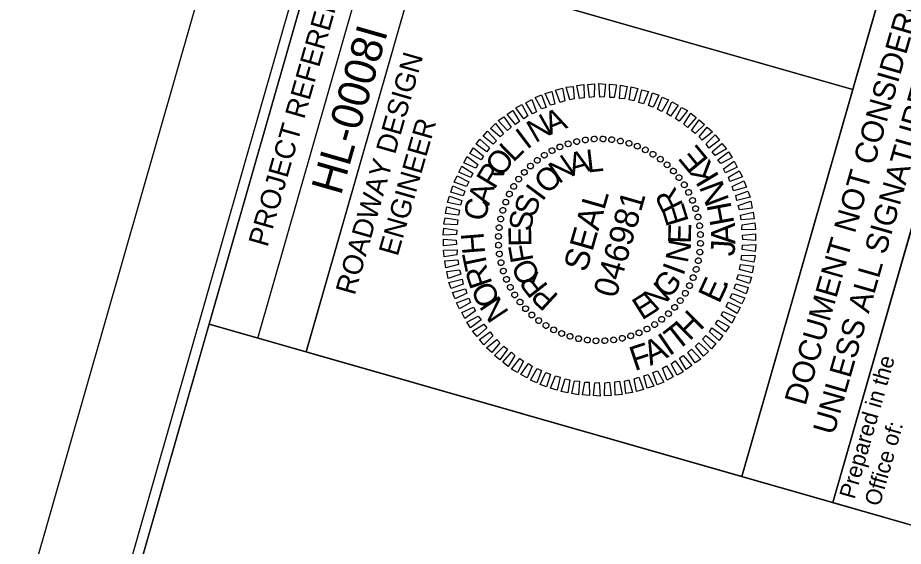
# Model space of a CAD drawing. Extents: x 2096988 to 2098509, y 687711 to 689775.
# Drawn here: x 2097368.1 to 2097587.9, y 689361.6 to 689492.9 of the extents above; entities that cross this region are included whole.
import ezdxf

# ---------------------------------------------------------------- set-up
doc = ezdxf.new("R2010")
doc.units = 0
for name, color, linetype in [('Sheet Block Title CELL', 7, 'Continuous'), ('Sheet Data Field CELL', 7, 'Continuous'), ('Sheet Layout Plan Border', 7, 'Continuous'), ('Sheet PE Seal Cell', 7, 'Continuous'), ('Sheet Plot Border Inside CELL', 7, 'Continuous'), ('Sheet Plot Border Outside CELL', 7, 'Continuous'), ('Sheet Profile CELL', 7, 'Continuous'), ('Sheet Sticker Exception Certification CELL', 7, 'Continuous')]:
    doc.layers.add(name, color=color, linetype=linetype)

msp = doc.modelspace()

# ---------------------------------------------------------------- linework, layer by layer
at = {"layer": 'Sheet Block Title CELL'}
msp.add_lwpolyline([(2097570.41, 689372.44), (2097625.47, 689564.78), (2097650.71, 689557.55), (2097595.66, 689365.22)], close=True, dxfattribs=at)
at = {"layer": 'Sheet Layout Plan Border'}
msp.add_lwpolyline([(2098117.8, 688054.49), (2097347.73, 688084.03), (2097057.83, 688167.01), (2097415.58, 689416.76), (2097595.66, 689365.22), (2097650.71, 689557.55), (2098480.09, 689320.13)], close=True, dxfattribs=at)
at = {"layer": 'Sheet PE Seal Cell'}
for p, q in [((2097508.97, 689462.59), (2097508.97, 689462.59)), ((2097511.11, 689462.81), (2097511.11, 689462.81)), ((2097513.3, 689462.81), (2097513.3, 689462.81)), ((2097515.52, 689462.59), (2097515.52, 689462.59)), ((2097502.65, 689460.86), (2097502.65, 689460.86)), ((2097504.68, 689461.58), (2097504.68, 689461.58)), ((2097506.82, 689462.16), (2097506.82, 689462.16)), ((2097517.67, 689462.28), (2097517.67, 689462.28)), ((2097519.8, 689461.73), (2097519.8, 689461.73)), ((2097521.88, 689460.98), (2097521.88, 689460.98)), ((2097498.78, 689458.8), (2097498.78, 689458.8)), ((2097500.65, 689459.87), (2097500.65, 689459.87)), ((2097523.85, 689460.05), (2097523.85, 689460.05)), ((2097525.74, 689459.04), (2097525.74, 689459.04)), ((2097495.31, 689456.1), (2097495.31, 689456.1)), ((2097497.01, 689457.49), (2097497.01, 689457.49)), ((2097527.57, 689457.79), (2097527.57, 689457.79)), ((2097529.24, 689456.37), (2097529.24, 689456.37)), ((2097493.81, 689454.5), (2097493.81, 689454.5)), ((2097530.84, 689454.87), (2097530.84, 689454.87)), ((2097492.39, 689452.82), (2097492.39, 689452.82)), ((2097532.23, 689453.18), (2097532.23, 689453.18)), ((2097491.14, 689451), (2097491.14, 689451)), ((2097533.54, 689451.4), (2097533.54, 689451.4)), ((2097534.62, 689449.53), (2097534.62, 689449.53)), ((2097490.13, 689449.1), (2097490.13, 689449.1)), ((2097535.61, 689447.53), (2097535.61, 689447.53)), ((2097488.46, 689445.06), (2097488.46, 689445.06)), ((2097489.2, 689447.13), (2097489.2, 689447.13)), ((2097536.33, 689445.5), (2097536.33, 689445.5)), ((2097487.9, 689442.93), (2097487.9, 689442.93)), ((2097536.91, 689443.36), (2097536.91, 689443.36)), ((2097487.59, 689440.78), (2097487.59, 689440.78)), ((2097537.33, 689441.21), (2097537.33, 689441.21)), ((2097487.37, 689438.56), (2097487.37, 689438.56)), ((2097537.55, 689439.07), (2097537.55, 689439.07)), ((2097487.37, 689436.37), (2097487.37, 689436.37)), ((2097512.46, 689437.72), (2097512.46, 689437.72)), ((2097537.55, 689436.88), (2097537.55, 689436.88)), ((2097487.59, 689434.23), (2097487.59, 689434.23)), ((2097537.33, 689434.66), (2097537.33, 689434.66)), ((2097488.02, 689432.08), (2097488.02, 689432.08)), ((2097537.03, 689432.51), (2097537.03, 689432.51)), ((2097488.6, 689429.94), (2097488.6, 689429.94)), ((2097536.47, 689430.38), (2097536.47, 689430.38)), ((2097489.32, 689427.91), (2097489.32, 689427.91)), ((2097535.72, 689428.3), (2097535.72, 689428.3)), ((2097490.31, 689425.91), (2097490.31, 689425.91)), ((2097534.79, 689426.33), (2097534.79, 689426.33)), ((2097491.38, 689424.04), (2097491.38, 689424.04)), ((2097533.78, 689424.44), (2097533.78, 689424.44)), ((2097492.7, 689422.26), (2097492.7, 689422.26)), ((2097531.11, 689420.94), (2097531.11, 689420.94)), ((2097532.53, 689422.61), (2097532.53, 689422.61)), ((2097494.08, 689420.56), (2097494.08, 689420.56)), ((2097495.68, 689419.07), (2097495.68, 689419.07)), ((2097529.62, 689419.34), (2097529.62, 689419.34)), ((2097497.36, 689417.65), (2097497.36, 689417.65)), ((2097499.18, 689416.4), (2097499.18, 689416.4)), ((2097526.14, 689416.64), (2097526.14, 689416.64)), ((2097527.92, 689417.95), (2097527.92, 689417.95)), ((2097501.08, 689415.39), (2097501.08, 689415.39)), ((2097503.05, 689414.46), (2097503.05, 689414.46)), ((2097522.27, 689414.58), (2097522.27, 689414.58)), ((2097524.27, 689415.56), (2097524.27, 689415.56)), ((2097505.12, 689413.71), (2097505.12, 689413.71)), ((2097507.25, 689413.15), (2097507.25, 689413.15)), ((2097509.4, 689412.85), (2097509.4, 689412.85)), ((2097511.63, 689412.63), (2097511.63, 689412.63)), ((2097513.81, 689412.63), (2097513.81, 689412.63)), ((2097515.95, 689412.85), (2097515.95, 689412.85)), ((2097518.1, 689413.27), (2097518.1, 689413.27)), ((2097520.25, 689413.86), (2097520.25, 689413.86))]:
    msp.add_line(p, q, dxfattribs=at)
for points in [[(2097505.14, 689472.47), (2097504.23, 689475.65), (2097505.9, 689475.85), (2097506.22, 689472.79)], [(2097507.49, 689472.84), (2097506.86, 689476.09), (2097508.57, 689476.28), (2097508.68, 689473.02)], [(2097509.99, 689473.06), (2097509.58, 689476.35), (2097511.22, 689476.45), (2097511.14, 689473.25)], [(2097512.52, 689473.17), (2097512.3, 689476.56), (2097513.97, 689476.4), (2097513.63, 689473.22)], [(2097514.99, 689473.09), (2097514.95, 689476.38), (2097516.66, 689476.2), (2097516.09, 689473.09)], [(2097517.42, 689472.86), (2097517.65, 689476.18), (2097519.32, 689475.85), (2097518.63, 689472.72)], [(2097498.06, 689470.24), (2097496.53, 689473.07), (2097498.11, 689473.71), (2097499.21, 689470.64)], [(2097500.34, 689471.14), (2097499, 689474.08), (2097500.65, 689474.59), (2097501.42, 689471.46)], [(2097502.67, 689471.83), (2097501.57, 689474.9), (2097503.28, 689475.4), (2097503.83, 689472.23)], [(2097519.81, 689472.49), (2097520.32, 689475.72), (2097521.99, 689475.35), (2097521, 689472.25)], [(2097522.23, 689471.85), (2097522.98, 689475.01), (2097524.62, 689474.55), (2097523.39, 689471.52)], [(2097524.62, 689471.11), (2097525.61, 689474.21), (2097527.17, 689473.66), (2097525.75, 689470.69)], [(2097495.84, 689469.05), (2097494.18, 689471.77), (2097495.66, 689472.59), (2097496.82, 689469.55)], [(2097526.86, 689470.21), (2097528.03, 689473.2), (2097529.61, 689472.54), (2097527.95, 689469.64)], [(2097529.2, 689469.12), (2097530.44, 689471.99), (2097531.98, 689471.19), (2097530.1, 689468.45)], [(2097491.65, 689466.4), (2097489.52, 689468.94), (2097490.93, 689469.89), (2097492.59, 689467.12)], [(2097493.67, 689467.8), (2097491.73, 689470.49), (2097493.21, 689471.31), (2097494.65, 689468.51)], [(2097531.33, 689467.84), (2097532.81, 689470.64), (2097534.3, 689469.85), (2097532.23, 689467.17)], [(2097533.43, 689466.46), (2097535.15, 689469.19), (2097536.46, 689468.14), (2097534.29, 689465.64)], [(2097489.65, 689464.85), (2097487.34, 689467.33), (2097488.71, 689468.29), (2097490.53, 689465.74)], [(2097535.27, 689464.89), (2097537.23, 689467.55), (2097538.51, 689466.41), (2097536.19, 689464.11)], [(2097486.07, 689461.45), (2097483.58, 689463.46), (2097484.68, 689464.76), (2097486.9, 689462.35)], [(2097487.81, 689463.34), (2097485.44, 689465.42), (2097486.67, 689466.63), (2097488.65, 689464.09)], [(2097537.21, 689463.3), (2097539.19, 689465.69), (2097540.48, 689464.54), (2097537.96, 689462.46)], [(2097484.54, 689459.55), (2097481.83, 689461.52), (2097482.79, 689462.7), (2097485.19, 689460.55)], [(2097538.94, 689461.55), (2097541.16, 689463.83), (2097542.23, 689462.48), (2097539.59, 689460.53)], [(2097483.06, 689457.63), (2097480.28, 689459.2), (2097481.19, 689460.56), (2097483.68, 689458.54)], [(2097540.45, 689459.56), (2097542.83, 689461.69), (2097543.96, 689460.37), (2097541.19, 689458.67)], [(2097481.77, 689455.5), (2097478.78, 689456.88), (2097479.64, 689458.4), (2097482.3, 689456.44)], [(2097541.87, 689457.59), (2097544.46, 689459.56), (2097545.4, 689458.14), (2097542.54, 689456.67)], [(2097480.54, 689453.2), (2097477.59, 689454.51), (2097478.28, 689456.03), (2097481.02, 689454.31)], [(2097543.21, 689455.39), (2097545.89, 689457.28), (2097546.65, 689455.76), (2097543.76, 689454.4)], [(2097544.44, 689453.32), (2097547.16, 689454.83), (2097547.98, 689453.35), (2097544.85, 689452.21)], [(2097479.5, 689451), (2097476.43, 689452.09), (2097477.17, 689453.59), (2097480.02, 689452.1)], [(2097545.38, 689450.97), (2097548.28, 689452.38), (2097548.92, 689450.79), (2097545.74, 689449.88)], [(2097478.66, 689448.64), (2097475.54, 689449.54), (2097476.04, 689451.11), (2097479.04, 689449.78)], [(2097546.3, 689448.73), (2097549.26, 689449.81), (2097549.82, 689448.3), (2097546.57, 689447.51)], [(2097477.95, 689446.35), (2097474.76, 689447), (2097475.26, 689448.57), (2097478.33, 689447.49)], [(2097546.9, 689446.27), (2097550, 689447.31), (2097550.34, 689445.6), (2097547.21, 689445.19)], [(2097477.51, 689443.88), (2097474.28, 689444.23), (2097474.55, 689445.92), (2097477.69, 689445.07)], [(2097477.14, 689441.49), (2097473.84, 689441.6), (2097474.15, 689443.23), (2097477.32, 689442.68)], [(2097547.46, 689443.88), (2097550.59, 689444.64), (2097550.84, 689442.96), (2097547.59, 689442.69)], [(2097477, 689439.03), (2097473.69, 689438.88), (2097473.82, 689440.62), (2097477.05, 689440.11)], [(2097547.86, 689441.47), (2097551.01, 689441.92), (2097551.17, 689440.32), (2097547.81, 689440.19)], [(2097547.96, 689438.9), (2097551.16, 689439.18), (2097551.16, 689437.56), (2097548, 689437.79)], [(2097476.97, 689436.54), (2097473.77, 689436.26), (2097473.76, 689437.88), (2097476.92, 689437.65)], [(2097547.92, 689436.41), (2097551.24, 689436.55), (2097551.11, 689434.82), (2097547.87, 689435.33)], [(2097477.06, 689433.97), (2097473.92, 689433.51), (2097473.75, 689435.12), (2097477.12, 689435.25)], [(2097477.47, 689431.56), (2097474.33, 689430.79), (2097474.09, 689432.48), (2097477.34, 689432.74)], [(2097547.79, 689433.95), (2097551.09, 689433.84), (2097550.78, 689432.21), (2097547.6, 689432.76)], [(2097478.03, 689429.16), (2097474.92, 689428.13), (2097474.58, 689429.84), (2097477.71, 689430.24)], [(2097547.42, 689431.56), (2097550.65, 689431.21), (2097550.37, 689429.52), (2097547.23, 689430.37)], [(2097478.62, 689426.71), (2097475.66, 689425.63), (2097475.11, 689427.14), (2097478.35, 689427.93)], [(2097546.97, 689429.09), (2097550.16, 689428.43), (2097549.66, 689426.86), (2097546.59, 689427.95)], [(2097479.54, 689424.47), (2097476.65, 689423.06), (2097476.01, 689424.65), (2097479.18, 689425.56)], [(2097546.26, 689426.8), (2097549.39, 689425.9), (2097548.88, 689424.33), (2097545.88, 689425.66)], [(2097480.48, 689422.12), (2097477.76, 689420.61), (2097476.94, 689422.09), (2097480.07, 689423.22)], [(2097545.43, 689424.43), (2097548.5, 689423.35), (2097547.76, 689421.84), (2097544.91, 689423.33)], [(2097481.71, 689420.05), (2097479.04, 689418.16), (2097478.28, 689419.68), (2097481.16, 689421.04)], [(2097544.38, 689422.24), (2097547.34, 689420.92), (2097546.64, 689419.41), (2097543.91, 689421.12)], [(2097483.06, 689417.84), (2097480.47, 689415.88), (2097479.52, 689417.3), (2097482.38, 689418.76)], [(2097543.15, 689419.94), (2097546.14, 689418.56), (2097545.29, 689417.04), (2097542.62, 689418.99)], [(2097484.47, 689415.88), (2097482.09, 689413.75), (2097480.96, 689415.06), (2097483.74, 689416.76)], [(2097541.87, 689417.81), (2097544.64, 689416.23), (2097543.73, 689414.88), (2097541.24, 689416.89)], [(2097485.98, 689413.89), (2097483.77, 689411.61), (2097482.7, 689412.95), (2097485.34, 689414.9)], [(2097540.38, 689415.89), (2097543.1, 689413.92), (2097542.13, 689412.74), (2097539.73, 689414.88)], [(2097487.72, 689412.14), (2097485.73, 689409.74), (2097484.45, 689410.89), (2097486.97, 689412.98)], [(2097537.11, 689412.1), (2097539.48, 689410.01), (2097538.25, 689408.81), (2097536.27, 689411.35)], [(2097538.85, 689413.99), (2097541.34, 689411.98), (2097540.24, 689410.68), (2097538.02, 689413.08)], [(2097489.65, 689410.55), (2097487.69, 689407.88), (2097486.41, 689409.03), (2097488.73, 689411.33)], [(2097535.28, 689410.59), (2097537.58, 689408.11), (2097536.22, 689407.15), (2097534.4, 689409.7)], [(2097491.49, 689408.98), (2097489.78, 689406.25), (2097488.46, 689407.3), (2097490.64, 689409.8)], [(2097493.59, 689407.6), (2097492.12, 689404.8), (2097490.63, 689405.59), (2097492.7, 689408.27)], [(2097531.26, 689407.63), (2097533.19, 689404.95), (2097531.71, 689404.12), (2097530.28, 689406.93)], [(2097533.27, 689409.03), (2097535.41, 689406.5), (2097533.99, 689405.55), (2097532.34, 689408.31)], [(2097495.72, 689406.31), (2097494.49, 689403.44), (2097492.95, 689404.25), (2097494.82, 689406.99)], [(2097498.06, 689405.23), (2097496.9, 689402.23), (2097495.32, 689402.89), (2097496.98, 689405.8)], [(2097529.08, 689406.39), (2097530.75, 689403.67), (2097529.26, 689402.85), (2097528.11, 689405.88)], [(2097500.3, 689404.33), (2097499.31, 689401.23), (2097497.75, 689401.78), (2097499.18, 689404.75)], [(2097502.69, 689403.59), (2097501.94, 689400.42), (2097500.31, 689400.89), (2097501.54, 689403.92)], [(2097522.25, 689403.61), (2097523.35, 689400.54), (2097521.65, 689400.04), (2097521.1, 689403.21)], [(2097524.58, 689404.29), (2097525.93, 689401.36), (2097524.27, 689400.85), (2097523.5, 689403.98)], [(2097526.87, 689405.2), (2097528.4, 689402.37), (2097526.81, 689401.73), (2097525.71, 689404.8)], [(2097505.11, 689402.95), (2097504.6, 689399.71), (2097502.94, 689400.09), (2097503.93, 689403.18)], [(2097507.5, 689402.58), (2097507.28, 689399.26), (2097505.6, 689399.58), (2097506.29, 689402.72)], [(2097509.93, 689402.35), (2097509.98, 689399.06), (2097508.26, 689399.24), (2097508.84, 689402.35)], [(2097512.4, 689402.27), (2097512.63, 689398.87), (2097510.96, 689399.04), (2097511.3, 689402.22)], [(2097514.93, 689402.37), (2097515.34, 689399.08), (2097513.7, 689398.98), (2097513.78, 689402.18)], [(2097517.44, 689402.59), (2097518.07, 689399.34), (2097516.35, 689399.16), (2097516.24, 689402.42)], [(2097519.78, 689402.96), (2097520.69, 689399.79), (2097519.02, 689399.59), (2097518.7, 689402.65)]]:
    msp.add_lwpolyline(points, close=True, dxfattribs=at)
for centre, major_axis in [((2097506.81, 689462.15), (-0.162, 0.701)), ((2097508.96, 689462.55), (-0.101, 0.713)), ((2097511.14, 689462.76), (-0.038, 0.719)), ((2097513.33, 689462.78), (0.025, 0.72)), ((2097515.51, 689462.61), (0.087, 0.715)), ((2097517.67, 689462.25), (0.149, 0.704)), ((2097500.68, 689459.86), (-0.338, 0.636)), ((2097502.65, 689460.8), (-0.282, 0.663)), ((2097504.7, 689461.57), (-0.223, 0.685)), ((2097519.78, 689461.71), (0.21, 0.689)), ((2097521.85, 689460.98), (0.269, 0.668)), ((2097523.84, 689460.07), (0.327, 0.642)), ((2097497.01, 689457.47), (-0.444, 0.567)), ((2097498.79, 689458.75), (-0.392, 0.604)), ((2097525.74, 689458.99), (0.381, 0.611)), ((2097527.55, 689457.76), (0.433, 0.575)), ((2097495.35, 689456.05), (-0.491, 0.526)), ((2097529.24, 689456.36), (0.482, 0.535)), ((2097493.82, 689454.49), (-0.535, 0.482)), ((2097530.8, 689454.83), (0.526, 0.491)), ((2097532.22, 689453.17), (0.567, 0.444)), ((2097491.19, 689451), (-0.611, 0.381)), ((2097492.43, 689452.8), (-0.575, 0.433)), ((2097533.49, 689451.39), (0.604, 0.392)), ((2097490.11, 689449.09), (-0.642, 0.327)), ((2097534.6, 689449.5), (0.636, 0.338)), ((2097489.2, 689447.1), (-0.668, 0.269)), ((2097535.54, 689447.53), (0.663, 0.282)), ((2097488.47, 689445.04), (-0.689, 0.21)), ((2097536.31, 689445.48), (0.685, 0.223)), ((2097487.93, 689442.92), (-0.704, 0.149)), ((2097536.9, 689443.37), (0.701, 0.162)), ((2097487.57, 689440.76), (-0.715, 0.087)), ((2097537.3, 689441.22), (0.713, 0.101)), ((2097487.4, 689438.58), (-0.72, 0.025)), ((2097537.51, 689439.04), (0.719, 0.038)), ((2097487.42, 689436.39), (-0.719, -0.038)), ((2097537.53, 689436.85), (0.72, -0.025)), ((2097487.63, 689434.22), (-0.713, -0.101)), ((2097537.36, 689434.67), (0.715, -0.087)), ((2097488.03, 689432.07), (-0.701, -0.162)), ((2097537, 689432.52), (0.704, -0.149)), ((2097488.61, 689429.96), (-0.685, -0.223)), ((2097536.45, 689430.4), (0.689, -0.21)), ((2097489.38, 689427.91), (-0.663, -0.282)), ((2097535.72, 689428.33), (0.668, -0.269)), ((2097490.32, 689425.93), (-0.636, -0.338)), ((2097533.74, 689424.44), (0.611, -0.381)), ((2097534.81, 689426.34), (0.642, -0.327)), ((2097491.43, 689424.05), (-0.604, -0.392)), ((2097492.71, 689422.27), (-0.567, -0.444)), ((2097532.5, 689422.63), (0.575, -0.433)), ((2097494.13, 689420.61), (-0.526, -0.491)), ((2097531.11, 689420.95), (0.535, -0.482)), ((2097495.69, 689419.07), (-0.482, -0.535)), ((2097527.91, 689417.96), (0.444, -0.567)), ((2097529.58, 689419.38), (0.491, -0.526)), ((2097497.38, 689417.68), (-0.433, -0.575)), ((2097499.18, 689416.44), (-0.381, -0.611)), ((2097524.25, 689415.58), (0.338, -0.636)), ((2097526.13, 689416.69), (0.392, -0.604)), ((2097501.09, 689415.37), (-0.327, -0.642)), ((2097503.08, 689414.46), (-0.269, -0.668)), ((2097505.14, 689413.73), (-0.21, -0.689)), ((2097520.22, 689413.87), (0.223, -0.685)), ((2097522.27, 689414.64), (0.282, -0.663)), ((2097507.26, 689413.18), (-0.149, -0.704)), ((2097509.42, 689412.82), (-0.087, -0.715)), ((2097511.6, 689412.65), (-0.025, -0.72)), ((2097513.79, 689412.67), (0.038, -0.719)), ((2097515.96, 689412.88), (0.101, -0.713)), ((2097518.12, 689413.28), (0.162, -0.701))]:
    msp.add_ellipse(centre, major_axis=major_axis, ratio=0.999708, dxfattribs=at)
at = {"layer": 'Sheet Plot Border Inside CELL'}
msp.add_lwpolyline([(2098027.36, 687729.29), (2098485.98, 689331.44), (2097471.62, 689621.81), (2097013, 688019.66)], close=True, dxfattribs=at)
at = {"layer": 'Sheet Plot Border Outside CELL'}
msp.add_lwpolyline([(2098045.36, 687710.62), (2098508.8, 689329.59), (2097451.28, 689632.31), (2096987.84, 688013.34)], close=True, dxfattribs=at)
at = {"layer": 'Sheet Profile CELL'}
for p, q in [((2097427.65, 689413.31), (2097482.7, 689605.64)), ((2097467.2, 689506.06), (2097575.31, 689475.11))]:
    msp.add_line(p, q, dxfattribs=at)
for points in [[(2097470.64, 689609.09), (2097057.83, 688167.01), (2098067.29, 687878.05), (2098480.09, 689320.13)], [(2097415.58, 689416.76), (2097470.64, 689609.09), (2097494.72, 689602.2), (2097439.66, 689409.87)], [(2097467.2, 689506.06), (2097494.72, 689602.2), (2097602.87, 689571.24), (2097575.35, 689475.1)], [(2097439.66, 689409.87), (2097467.2, 689506.06), (2097575.35, 689475.1), (2097547.82, 689378.91)]]:
    msp.add_lwpolyline(points, close=True, dxfattribs=at)
at = {"layer": 'Sheet Sticker Exception Certification CELL'}
for p, q in [((2097547.82, 689378.91), (2097602.87, 689571.22)), ((2097625.46, 689564.76), (2097570.41, 689372.44)), ((2097570.41, 689372.44), (2097547.82, 689378.91))]:
    msp.add_line(p, q, dxfattribs=at)

# ---------------------------------------------------------------- texts
at = {"layer": 'Sheet Block Title CELL'}
for s, height, p in [('Prepared in the ', 4.0012, (2097575.74, 689373.13)), ('Office of:', 4.001, (2097581.99, 689371.34))]:
    msp.add_text(s, height=height, rotation=74.0259, dxfattribs=at).set_placement(p)
at = {"layer": 'Sheet Data Field CELL'}
msp.add_text('HL-0008I', height=7.75, rotation=74.0259, dxfattribs=at).set_placement((2097448.28, 689448.56))
at = {"layer": 'Sheet PE Seal Cell'}
for s, height, rotation, p in [('A', 5.64, 22.643, (2097500.19, 689463.7)), ('N', 5.64, 29.8448, (2097496.54, 689461.68)), ('I', 5.64, 37.046, (2097494.46, 689460.03)), ('L', 5.64, 44.2468, (2097491.04, 689456.8)), ('E', 6, 129.5189, (2097539.77, 689457.57)), ('O', 5.64, 51.4471, (2097488.05, 689453.08)), ('N', 5.64, 34.5025, (2097502.36, 689451.48)), ('A', 5.64, 15.7862, (2097505.64, 689453.5)), ('L', 5.64, 6.4267, (2097509.5, 689454.43)), ('R', 5.64, 58.647, (2097486.4, 689450.07)), ('K', 6, 121.235, (2097542.35, 689453.43)), ('O', 5.64, 43.8594, (2097499.51, 689448.81)), ('I', 5.64, 53.2155, (2097498.29, 689447.08)), ('N', 6, 110.5092, (2097544.75, 689447.59)), ('A', 5.64, 73.0462, (2097485.06, 689446.08)), ('R', 5.64, 116.5073, (2097533.41, 689446.39)), ('C', 5.64, 80.2458, (2097484.26, 689442.2)), ('S', 5.64, 71.9263, (2097496.44, 689443.14)), ('SEAL', 5.998, 74.0259, (2097509.22, 689429.49)), ('046981', 5.998, 74.0259, (2097516.59, 689423.04)), ('E', 5.64, 107.15, (2097534.69, 689442.33)), ('H', 6, 100.5252, (2097545.97, 689441.85)), ('S', 5.64, 81.2815, (2097495.49, 689439.66)), ('E', 5.64, 90.637, (2097495.55, 689436.06)), ('E', 5.64, 88.4377, (2097535.11, 689436.7)), ('A', 6, 91.6849, (2097546.21, 689436.65)), ('H', 5.64, 94.6454, (2097484.09, 689434.35)), ('F', 5.64, 99.9929, (2097496.11, 689432.57)), ('N', 5.64, 79.0823, (2097534.32, 689431.77)), ('J', 6, 86.427, (2097545.97, 689433.56)), ('T', 5.64, 101.8457, (2097484.78, 689430.77)), ('O', 5.64, 118.7071, (2097498.04, 689428.58)), ('I', 5.64, 69.7271, (2097533.25, 689428.59)), ('R', 5.64, 109.0464, (2097485.96, 689426.89)), ('R', 5.64, 128.0655, (2097499.92, 689426.23)), ('G', 5.64, 51.0161, (2097529.62, 689422.82)), ('E', 6, 65.0836, (2097542.16, 689421.65)), ('O', 5.64, 116.2476, (2097487.99, 689422.72)), ('N', 5.64, 41.6598, (2097526.42, 689419.79)), ('.', 6, 72.1929, (2097543.92, 689425.45)), ('N', 5.64, 123.4494, (2097490.15, 689419.71)), ('P', 5.64, 137.4248, (2097502.55, 689423.81)), ('E', 5.64, 32.3028, (2097522.99, 689417.64)), ('H', 6, 44.8992, (2097534.79, 689412.39)), ('T', 6, 38.099, (2097531.63, 689409.92)), ('I', 6, 34.297, (2097529.75, 689408.71)), ('F', 6, 18.4401, (2097521.16, 689405.1)), ('A', 6, 25.4567, (2097525.08, 689406.4))]:
    msp.add_text(s, height=height, rotation=rotation, dxfattribs=at).set_placement(p)
at = {"layer": 'Sheet Profile CELL'}
for s, height, p in [('PROJECT REFERENCE NO.', 5.0001, (2097430.05, 689435.73)), ('ROADWAY DESIGN', 5.0001, (2097451.69, 689423.76)), ('ENGINEER', 5, (2097462.37, 689433.45))]:
    msp.add_text(s, height=height, rotation=74.0259, dxfattribs=at).set_placement(p)
at = {"layer": 'Sheet Sticker Exception Certification CELL'}
for s, p in [('UNLESS ALL SIGNATURES COMPLETED', (2097570.63, 689389.02)), ('DOCUMENT NOT CONSIDERED FINAL', (2097563.57, 689396.32))]:
    msp.add_text(s, height=5.5, rotation=74.0259, dxfattribs=at).set_placement(p)

doc.saveas('drawing.dxf')
